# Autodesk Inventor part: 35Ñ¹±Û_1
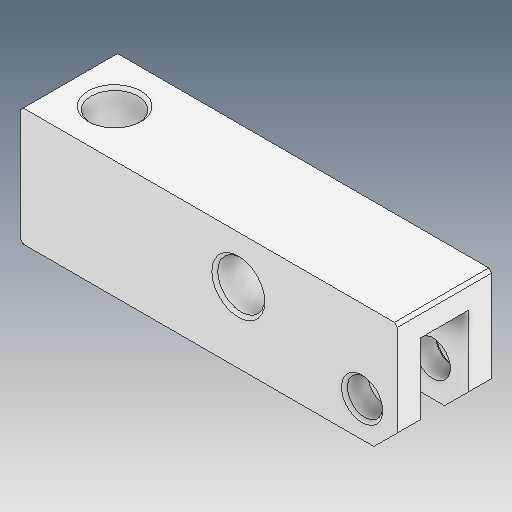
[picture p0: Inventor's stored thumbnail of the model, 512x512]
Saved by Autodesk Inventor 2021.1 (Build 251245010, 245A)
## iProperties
Created: 2021-05
Part Number: 35Ñ¹±Û_1
Material: Ogólny
Document SubType Name: Modeling
Designer: user
Density: 1 g/cm^3
Appearance: Domyślna
Author: user
Revision Number: ÈÎºÎ
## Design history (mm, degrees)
feature "ÊäÈë1"
node "Bryła1"
